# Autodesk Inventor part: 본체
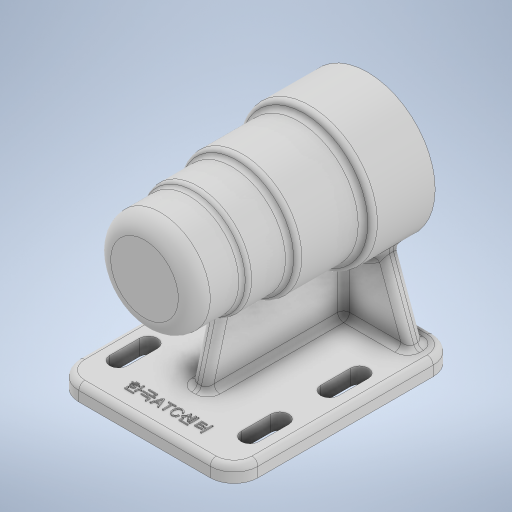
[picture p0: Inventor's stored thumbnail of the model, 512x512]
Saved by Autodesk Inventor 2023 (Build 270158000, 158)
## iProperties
Created: 2022-07
Part Number: 본체
Material: 일반
Document SubType Name: Modeling
Designer: owner
Density: 1 g/cm^3
Appearance: 기본값
Author: owner
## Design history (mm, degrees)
sketch "스케치1"
  geometry: L1 (33, 56)-(-33, 56); L2 (-45, 44)-(-45, -44); L3 (-33, -56)-(33, -56); L4 (45, -44)-(45, 44); L5 (45, 56)-(-45, -56); L6 (-45, 56)-(45, -56); A1 r 12 centre (33, 44) between (45, 44) and (33, 56); A2 r 12 centre (33, -44) between (33, -56) and (45, -44); A3 r 12 centre (-33, 44) between (-33, 56) and (-45, 44); A4 r 12 centre (-33, -44) between (-45, -44) and (-33, -56); 1 further point
  constraints: 12 end point, 8 point on circle, 8 point on line, 8 tangent, 4 centre point, 3 equal radius, 2 midpoint, 2 parallel, 1 horizontal, 1 perpendicular
  dimensions: "d0" = 90 distance of L6.end L5.end; "d1" = 112 distance of L5.end L6.start; "d2" = 12 radius of A1
extrude "돌출1" new body sketch "스케치1" distance "d3" = 8; taper "d4" = 0 deg
sketch "스케치2"
  geometry: L1 (-33, -36)-(-33, -21); L2 (-28.5, -36)-(-28.5, -21); L3 (-37.5, -21)-(-37.5, -36); L4 (-33, -56)-(33, -56) reference; L5 (-33, 4)-(-33, 19); L6 (-28.5, 4)-(-28.5, 19); L7 (-37.5, 19)-(-37.5, 4); A1 r 4.5 centre (-33, -36) between (-37.5, -36) and (-28.5, -36); A2 r 4.5 centre (-33, -21) between (-28.5, -21) and (-37.5, -21); A3 r 4.5 centre (-33, 4) between (-37.5, 4) and (-28.5, 4); A4 r 4.5 centre (-33, 19) between (-28.5, 19) and (-37.5, 19); 3 further points
  constraints: 16 end point, 8 point on circle, 8 tangent, 4 centre point, 2 midpoint, 2 parallel, 2 vertical
  dimensions: "d5" = 20 distance from line of L4 L1.start; "d6" = 15 distance of L1.start L1.end; "d7" = 9 distance between parallel lines of L2 L3; "d8" = 33 distance from line of point (0, 0) L1; "d9" = 9 distance between parallel lines of L6 L7; "d10" = 15 distance of L5.start L5.end; "d11" = 25 distance of L5.start L1.end; "d12" = 33 distance from line of point (0, 0) L5
extrude "돌출2" cut sketch "스케치2" distance "d13" = 8; taper "d14" = 0 deg
sketch "스케치4"
  geometry: L1 (0, 0)-(147.887, 0); L2 (70, 56)-(70, -56); L3 (0, -56)-(8, -56) reference; L4 (91, -56)-(91, -41); L5 (91, -41)-(94, -41); L6 (94, -41)-(94, 13); L7 (94, 13)-(91, 13); L8 (91, 13)-(91, 25); L9 (91, 25)-(87.5, 25); L10 (87.5, 25)-(87.5, 43); L11 (87.5, 43)-(86, 43); L12 (86, 43)-(86, 47); L13 (86, 47)-(80.5, 47); L14 (80.5, 47)-(80.5, 50); L15 (80.5, 50)-(70, 50); L16 (70, 50)-(70, 56); L17 (70, 56)-(95, 56); L18 (95, 56)-(95, 32); L19 (95, 32)-(97, 32); L20 (97, 32)-(97, 10); L21 (97, 10)-(100, 10); L22 (100, 10)-(100, -24); L23 (100, -24)-(104, -24); L24 (104, -24)-(104, -56); L25 (104, -56)-(91, -56); 1 further point
  constraints: 48 end point, 17 perpendicular, 3 horizontal, 3 point on line, 2 horizontal alignment, 2 vertical, 1 collinear, 1 midpoint
  dimensions: "d40" = 70 distance from line of L1.start L2; "d41" = 147.88724 distance of L1.start L1.end; "d42" = 112 distance of L2.start L2.end; "d43" = 15 distance of L4.start L4.end; "d44" = 42 diameter of L4 L2; "d45" = 48 diameter of L6 L2; "d46" = 54 distance between parallel lines of L5 L7; "d47" = 12 distance between parallel lines of L9 L7; "d48" = 35 diameter of L10 L2; "d49" = 32 diameter of L12 L2; "d50" = 21 diameter of L14 L2; "d51" = 18 distance between parallel lines of L11 L9; "d52" = 4 distance between parallel lines of L13 L11; "d53" = 3 distance between parallel lines of L13 L15; "d54" = 68 diameter of L24 L2; "d55" = 80 distance between parallel lines of L17 L23; "d56" = 60 diameter of L22 L2; "d57" = 54 diameter of L20 L2; "d58" = 50 diameter of L18 L2; "d59" = 46 distance between parallel lines of L17 L21; "d60" = 24 distance between parallel lines of L17 L19
revolve "회전1" sketch "스케치4" stored, may be unused: angle "d61" = 90 deg
fillet "모깎기1" dims "d62" = 8
node "작업 평면1"
sketch "스케치8"
  geometry: L1 (-4, 8)-(9.591, 45.342); L2 (-4.5, 8)-(4.5, 8) reference; L3 (0, 8)-(-12, 8) reference; L4 (33, 0)-(33, 70); L5 (70, 8)-(56.409, 45.342); L6 (70.5, 8)-(70.5, 0) reference; L7 (-4.5, 8)-(70.5, 8); C1 r 10.5 at (33, 70) reference; 4 further points
  constraints: 8 end point, 2 symmetric about line, 1 point on line, 2 other
  dimensions: "d71" = 8 distance of L3.end L1.start; "d72" = 110 deg angle of L3 L1
extrude "돌출3" join sketch "스케치8" distance "d73" = 8; taper "d74" = 0 deg
sketch "스케치14" dims "d91" = 52
  geometry: C1 r 24 at (0, 0) reference; 3 further points
  constraints: 2 horizontal alignment, 1 coincident, 2 other
hole "구멍1" sketch "스케치14" at (-26, 0) diameter "d84" = 3.242; stored, may be unused: countersink angle "d88" = 90 deg, drill point angle "d90" = 118 deg; dims "d85" = 8, "d86" = 4, "d87" = 2, "d89" = 11
fillet "모깎기2" dims "d95" = 3
chamfer "모따기1" distance "d96" = 1; stored, may be unused: second distance "d97" = 2, angle "d98" = 45 deg
sketch "스케치17"
  geometry: 1 further point
sketch "스케치18"
  geometry: 1 further point
sketch "스케치19"
  geometry: L1 (-33, -56)-(33, -56) reference; 2 further points
  constraints: 1 vertical alignment, 1 other
  dimensions: "d104" = 12 distance from line of L1 point (0, -44)
feature "엠보싱1" sketch "스케치19" dims "d105" = 0.5, "d106" = 0
sketch "스케치26"
  geometry: L1 (8, 29)-(45.342, 18.994); L2 (8, -48)-(45.342, -48) reference; L3 (8, 21)-(8, 36) reference; L4 (45.342, 18.994)-(45.342, -48); L5 (45.342, -40)-(8, -40) reference; L6 (0, -56)-(0, -44) reference; L7 (0, -48)-(45.342, -48); 1 further point
  constraints: 6 end point, 2 perpendicular, 2 point on line
  dimensions: "d127" = 77 distance from line of L2 L1.start; "d128" = 105 deg angle of L3 L1
feature "리브2" sketch "스케치26" dims "d129" = 1, "d130" = 8, "d131" = 0, "d132" = 0, "d133" = 1, "d134" = 1
fillet "모깎기3" dims "d135" = 3
fillet "모깎기4" dims "d136" = 3
node "솔리드1"
mirror "미러1"
pattern_circular "원형 패턴1" dims angle "d93" = 360 deg
feature "A9D066F2-1C7D-4E18-AEED-F7BC21143FA4" dims "d84" = 3.242, "d85" = 8, "d86" = 4, "d87" = 2, "d88" = 90 deg, "d89" = 11, "d90" = 118 deg
other parameters: "d70" = -8
